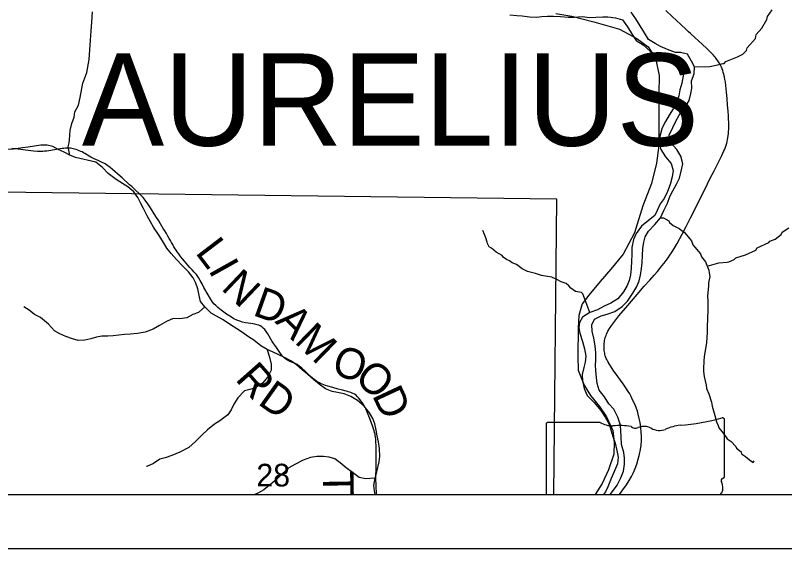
# Model space of a CAD drawing. Extents: x 0 to 34, y 0 to 22.
# Drawn here: x 6.729 to 8.15, y 14 to 14.985 of the extents above; entities that cross this region are included whole.
import ezdxf

# ---------------------------------------------------------------- set-up
doc = ezdxf.new("R2010")
doc.units = 0
for name, color, linetype in [('GM_X_Corporation_Text', 7, 'Continuous'), ('GM_X_Major_River', 7, 'Continuous'), ('GM_X_Minor_River', 7, 'Continuous'), ('GM_X_Rail_Line', 7, 'Continuous'), ('GM_X_Section_Text', 7, 'Continuous'), ('GM_X_State_Location', 7, 'Continuous'), ('GM_X_State_Route', 7, 'Continuous'), ('GM_X_State_Shield', 7, 'Continuous'), ('GM_X_Township_Road', 7, 'Continuous'), ('GM_X_Township_Road_Text', 7, 'Continuous'), ('GM_X_Township_Text', 7, 'Continuous'), ('SH_Cut_Line', 7, 'Continuous'), ('SH_Data', 7, 'Continuous')]:
    doc.layers.add(name, color=color, linetype=linetype)

msp = doc.modelspace()

# ---------------------------------------------------------------- linework, layer by layer
at = {"layer": 'GM_X_Corporation_Text'}
msp.add_line((7.8091, 14.2331), (7.7125, 14.2331), dxfattribs=at)
for points in [[(7.7093, 14.2297), (7.7093, 14.1), (8.0309, 14.1)], [(8.0389, 14.1334), (8.0389, 14.1334), (8.0389, 14.1334), (8.0389, 14.2383)]]:
    msp.add_lwpolyline(points, dxfattribs=at)
for centre, major_axis, start_param, end_param in [((7.9215, 14.506), (0.3495, 0), 4.814394, 5.042369), ((8.0353, 14.2385), (0.00367, 0), 6.197627, 7.989034), ((7.7131, 14.2301), (0.00382, 0), 1.727492, 3.291633), ((7.8321, 14.2564), (0.037, 0), 4.042888, 4.731792), ((7.8444, 14.1208), (0.133, 0), 1.404758, 1.657859), ((7.8745, 14.2311), (0.0107, 0), 3.836095, 5.185415), ((7.8902, 14.208), (0.0222, 0), 0.950623, 2.079405), ((7.9661, 14.172), (0.0703, 0), 1.699012, 2.107814), ((7.9189, 14.2397), (0.0267, 0), 4.08156, 5.145723), ((8.0381, 14.1257), (0.00568, 0), 1.883978, 3.671073), ((8.035, 14.133), (0.00393, 0), 5.05454, 6.418171), ((8.0019, 14.1125), (0.0341, 0), 5.934695, 6.695948), ((8.0521, 14.0896), (0.0248, 0), 2.387724, 2.589166)]:
    msp.add_ellipse(centre, major_axis=major_axis, ratio=0.8, start_param=start_param, end_param=end_param, dxfattribs=at)
at = {"layer": 'GM_X_Major_River'}
for points in [[(7.6424, 14.9858), (7.6553, 14.9844), (7.6648, 14.9838), (7.6784, 14.9825), (7.6917, 14.9819), (7.7015, 14.9828), (7.7118, 14.9837), (7.7232, 14.9835), (7.7357, 14.9829), (7.7501, 14.9819), (7.7615, 14.9817), (7.7766, 14.9827)], [(7.7766, 14.9827), (7.7895, 14.9813), (7.8013, 14.9815), (7.8138, 14.9824), (7.8236, 14.9825), (7.8377, 14.9801), (7.8506, 14.9765), (7.8599, 14.9637), (7.8684, 14.9494), (7.8754, 14.9385), (7.8888, 14.9307), (7.9015, 14.9191), (7.9114, 14.9117), (7.924, 14.9065), (7.9339, 14.9033), (7.9465, 14.8993), (7.956, 14.8967), (7.9633, 14.8847), (7.9627, 14.8733), (7.9603, 14.86), (7.9566, 14.8474), (7.9545, 14.8364), (7.9505, 14.8246), (7.9442, 14.812), (7.9368, 14.8009), (7.9298, 14.789), (7.9235, 14.7772), (7.9195, 14.762), (7.9182, 14.7498), (7.9214, 14.737), (7.9299, 14.7238), (7.9403, 14.7114), (7.9443, 14.6982), (7.9425, 14.6864), (7.9382, 14.6727), (7.9338, 14.6598), (7.9272, 14.6464), (7.9201, 14.6368), (7.9142, 14.6246), (7.9101, 14.6151), (7.8955, 14.6035), (7.8854, 14.5958), (7.8757, 14.582), (7.8709, 14.5709), (7.8677, 14.5561), (7.8679, 14.5436), (7.8673, 14.5303), (7.8663, 14.5189), (7.865, 14.5056), (7.8625, 14.4954), (7.8588, 14.4858), (7.8525, 14.474), (7.8421, 14.4613), (7.8289, 14.4532), (7.8165, 14.4477), (7.8041, 14.4411), (7.7901, 14.4363), (7.7766, 14.4278), (7.7707, 14.4179), (7.77, 14.408), (7.7717, 14.3978), (7.7764, 14.3823), (7.7804, 14.3687), (7.7829, 14.3555), (7.7815, 14.3441), (7.779, 14.3346), (7.7761, 14.3216), (7.7767, 14.3091), (7.7799, 14.2955), (7.7854, 14.2831), (7.7981, 14.2696), (7.8104, 14.255), (7.8185, 14.2426), (7.8259, 14.2301), (7.8287, 14.2192), (7.8323, 14.2071), (7.837, 14.1946), (7.8398, 14.181), (7.8427, 14.1689), (7.8409, 14.1564), (7.8354, 14.1438), (7.8292, 14.1297), (7.8233, 14.1144), (7.8189, 14.1049), (7.8154, 14.1)], [(7.8279, 14.1), (7.834, 14.1077), (7.8407, 14.1173), (7.8474, 14.1307), (7.8521, 14.1429), (7.8542, 14.1558), (7.8544, 14.1668), (7.8532, 14.1774), (7.8488, 14.1925), (7.8478, 14.2069), (7.8473, 14.2168), (7.8468, 14.2278), (7.8417, 14.2425), (7.8346, 14.2576), (7.8254, 14.2673), (7.8173, 14.2801), (7.8076, 14.2928), (7.8037, 14.3049), (7.8024, 14.3163), (7.8011, 14.3292), (7.8005, 14.3386), (7.8012, 14.3481), (7.801, 14.3618), (7.7997, 14.3747), (7.7972, 14.3887), (7.7944, 14.4019), (7.7938, 14.4136), (7.799, 14.4236), (7.8111, 14.4298), (7.822, 14.433), (7.836, 14.4377), (7.8499, 14.447), (7.8596, 14.457), (7.8693, 14.4716), (7.8767, 14.4842), (7.8811, 14.4948), (7.8836, 14.5051), (7.8857, 14.5173), (7.8867, 14.5279), (7.8876, 14.5416), (7.8882, 14.5545), (7.8896, 14.5663), (7.8925, 14.5758), (7.8984, 14.5865), (7.91, 14.5988), (7.9204, 14.6111), (7.9271, 14.6244), (7.9337, 14.6382), (7.9381, 14.6504), (7.9433, 14.661), (7.9499, 14.6733), (7.9555, 14.6843), (7.9591, 14.6969), (7.9619, 14.711), (7.9579, 14.725), (7.9509, 14.7374), (7.9394, 14.7501), (7.9369, 14.7637), (7.9432, 14.7779), (7.9483, 14.7885), (7.9554, 14.8008), (7.9654, 14.8142), (7.9736, 14.8279), (7.9768, 14.8409), (7.9786, 14.8504), (7.9777, 14.864), (7.9828, 14.877), (7.9834, 14.8899), (7.9779, 14.9001), (7.9705, 14.9132), (7.9576, 14.9165), (7.9481, 14.9163), (7.9336, 14.9218), (7.9207, 14.9277), (7.9107, 14.9329), (7.8985, 14.9403), (7.8911, 14.9524), (7.883, 14.9659), (7.8749, 14.9787), (7.8664, 14.9907)]]:
    msp.add_lwpolyline(points, dxfattribs=at)
at = {"layer": 'GM_X_Minor_River'}
for points in [[(7.9834, 14.8899), (8.0117, 14.8906), (8.0235, 14.893), (8.0356, 14.8959), (8.0382, 14.8963), (8.0412, 14.8998), (8.0631, 14.9081), (8.0725, 14.9132), (8.0796, 14.9201), (8.081, 14.9247), (8.0959, 14.942), (8.0976, 14.9497), (8.1081, 14.9616), (8.1173, 14.9773), (8.1183, 14.9827), (8.1272, 14.9953)], [(6.8294, 14.7267), (6.8261, 14.7419), (6.8283, 14.7492), (6.8289, 14.7553), (6.8298, 14.772), (6.8333, 14.785), (6.8377, 14.7972), (6.8386, 14.8067), (6.8456, 14.819), (6.8484, 14.8331), (6.8533, 14.8598), (6.8609, 14.8796), (6.8651, 14.9033), (6.8675, 14.939), (6.8687, 14.9565), (6.8699, 14.9721), (6.8711, 14.9915)], [(6.8402, 14.7225), (6.8294, 14.7267), (6.8189, 14.732), (6.8077, 14.7374), (6.798, 14.7427), (6.7878, 14.7449), (6.7757, 14.7453), (6.7642, 14.7435), (6.7524, 14.7416), (6.7417, 14.7405), (6.7302, 14.7382), (6.7207, 14.7374), (6.7097, 14.7382), (6.6988, 14.7424), (6.6887, 14.7465), (6.677, 14.7481), (6.6663, 14.7481), (6.6554, 14.7504), (6.6437, 14.7538), (6.6147, 14.7804)], [(7.3933, 14.1), (7.3921, 14.1069), (7.3913, 14.1168), (7.3933, 14.13), (7.3964, 14.1417), (7.4008, 14.1605), (7.4019, 14.1704), (7.4013, 14.1852), (7.3994, 14.1971), (7.3975, 14.2081), (7.3956, 14.2189), (7.3926, 14.2307), (7.3892, 14.2404), (7.3831, 14.2505), (7.3729, 14.263), (7.3607, 14.2737), (7.3484, 14.2809), (7.3364, 14.2859), (7.324, 14.2886), (7.3138, 14.2905), (7.3018, 14.2951), (7.2899, 14.3035), (7.2799, 14.3115), (7.2682, 14.3225), (7.2586, 14.3305), (7.2482, 14.3396), (7.2375, 14.3468), (7.2263, 14.3533), (7.2039, 14.3632), (7.1941, 14.3677), (7.1822, 14.3746), (7.1693, 14.3849), (7.1592, 14.3913), (7.1485, 14.3989), (7.1377, 14.4058), (7.1243, 14.4146), (7.1124, 14.4223), (7.1002, 14.4295), (7.0905, 14.4348), (7.0787, 14.4463), (7.0711, 14.4564), (7.0684, 14.4675), (7.0658, 14.4801), (7.0624, 14.4905), (7.0574, 14.5002), (7.0487, 14.5115), (7.0384, 14.5218), (7.0267, 14.534), (7.0164, 14.545), (7.0088, 14.5551), (7.0009, 14.5687), (6.9933, 14.5804), (6.9839, 14.594), (6.9782, 14.6037), (6.9721, 14.6149), (6.9658, 14.6281), (6.96, 14.6385), (6.9551, 14.6486), (6.9474, 14.6587), (6.9364, 14.6682), (6.9267, 14.6743), (6.9148, 14.6815), (6.9004, 14.6927), (6.8898, 14.7041), (6.8776, 14.714), (6.8402, 14.7225)], [(7.9204, 14.6111), (7.9263, 14.611), (7.9358, 14.6052), (7.937, 14.6022), (7.9443, 14.597), (7.955, 14.591), (7.965, 14.5836), (7.9778, 14.5682), (7.9802, 14.5611), (7.9946, 14.5446), (7.9962, 14.5389), (8.0036, 14.5299), (8.0099, 14.5144), (8.0104, 14.5095), (8.012, 14.5027), (8.0095, 14.4909), (8.0096, 14.4855), (8.0077, 14.4665), (8.0079, 14.457), (8.0078, 14.4403), (8.0068, 14.4099), (8.007, 14.3993), (8.0054, 14.3806), (8.0013, 14.3543), (8.001, 14.3467), (7.9998, 14.3323), (7.9999, 14.327), (8.0012, 14.3179), (8.0052, 14.3016), (8.0057, 14.2959), (8.0101, 14.2861), (8.0149, 14.2702), (8.0158, 14.2634), (8.021, 14.246), (8.0242, 14.2343), (8.0274, 14.2271), (8.0282, 14.2229), (8.034, 14.2162), (8.0422, 14.206), (8.0438, 14.203), (8.0514, 14.1978), (8.06, 14.1889), (8.0611, 14.1858), (8.0696, 14.1787), (8.0704, 14.1753), (8.0774, 14.1701), (8.0851, 14.1638), (8.0893, 14.1608), (8.092, 14.159), (8.0934, 14.162)], [(7.7901, 14.4363), (7.7772, 14.4709), (7.7745, 14.4731), (7.7638, 14.4752), (7.7592, 14.4782), (7.755, 14.4811), (7.7515, 14.4853), (7.7461, 14.4897), (7.737, 14.4926), (7.7301, 14.4963), (7.7197, 14.5011), (7.7117, 14.5025), (7.7007, 14.5046), (7.6896, 14.5082), (7.6747, 14.5118), (7.6652, 14.5166), (7.6548, 14.5248), (7.6467, 14.5281), (7.6418, 14.5314), (7.6364, 14.534), (7.6299, 14.5384), (7.6283, 14.5414), (7.6172, 14.5474), (7.6083, 14.5552), (7.6041, 14.5574), (7.6013, 14.5634), (7.6002, 14.5661), (7.5977, 14.574), (7.5954, 14.5801), (7.5926, 14.5876)], [(8.0069, 14.5218), (8.0283, 14.528), (8.0438, 14.529), (8.0468, 14.5294), (8.057, 14.5342), (8.06, 14.5372), (8.0777, 14.5428), (8.0966, 14.5515), (8.0992, 14.5553), (8.1206, 14.5652), (8.1229, 14.5679), (8.1323, 14.5718), (8.1435, 14.5803), (8.1457, 14.5846), (8.1577, 14.5927)], [(7.0787, 14.4463), (7.0673, 14.436), (7.0566, 14.4322), (7.0457, 14.4265), (7.0327, 14.4247), (7.0206, 14.4248), (7.0078, 14.4195), (6.995, 14.412), (6.9834, 14.4055), (6.9688, 14.4), (6.9543, 14.3975), (6.9417, 14.3964), (6.9306, 14.3956), (6.9199, 14.3941), (6.9096, 14.393), (6.8994, 14.3922), (6.8883, 14.3922), (6.8784, 14.3907), (6.868, 14.3876), (6.8573, 14.3849), (6.8448, 14.3846), (6.8346, 14.3873), (6.8218, 14.3915), (6.811, 14.3965), (6.8013, 14.4025), (6.7903, 14.4143), (6.7752, 14.4266), (6.764, 14.4323), (6.754, 14.4406), (6.7443, 14.4467)], [(7.1941, 14.3677), (7.1989, 14.3512), (7.2012, 14.3409), (7.2012, 14.3295), (7.1954, 14.3175), (7.1851, 14.3057), (7.1727, 14.297), (7.1619, 14.294), (7.1519, 14.2913), (7.1401, 14.2788), (7.1321, 14.2666), (7.1272, 14.2565), (7.1211, 14.2468), (7.1067, 14.2363), (7.0966, 14.2298), (7.0837, 14.2193), (7.0739, 14.2101), (7.0613, 14.198), (7.0491, 14.187), (7.0325, 14.1781), (7.0178, 14.1718), (7.0055, 14.1677), (6.9955, 14.165), (6.9839, 14.1574), (6.9719, 14.1518), (6.9711, 14.1518)], [(7.3933, 14.13), (7.3758, 14.1287), (7.3641, 14.1314), (7.3519, 14.1406), (7.34, 14.1494), (7.3289, 14.1585), (7.3189, 14.1661), (7.3088, 14.1691), (7.2982, 14.1699), (7.286, 14.1699), (7.2742, 14.1684), (7.2607, 14.1632), (7.2452, 14.1554), (7.234, 14.1493), (7.2214, 14.1384), (7.212, 14.1285), (7.201, 14.119), (7.1877, 14.1088), (7.178, 14.1031), (7.171, 14.1)]]:
    msp.add_lwpolyline(points, dxfattribs=at)
at = {"layer": 'GM_X_Rail_Line'}
for points in [[(4.5781, 14.1), (8.76, 14.1), (8.766, 14.6043), (8.767, 14.6265), (8.77, 15.1835), (8.7708, 15.6025), (8.369, 15.6108), (7.8392, 15.6096), (7.7355, 15.6105), (7.7434, 15.892), (7.7526, 15.9181), (7.756, 15.9342), (7.7538, 15.9954), (7.7446, 16.1373), (7.7377, 16.1663), (7.7376, 16.622), (7.6814, 16.6224), (7.149, 16.6283), (5.9824, 16.6436)], [(7.7272, 14.9881), (7.7567, 14.9837), (7.7973, 14.9733), (7.845, 14.9594), (7.8767, 14.9422), (7.8976, 14.9267), (7.9115, 14.9056), (7.9183, 14.8736), (7.9176, 14.8404), (7.9176, 14.7444), (7.9132, 14.7119), (7.9043, 14.6743), (7.8881, 14.6329), (7.8723, 14.583), (7.8516, 14.5439), (7.8291, 14.5163), (7.8091, 14.4934), (7.7883, 14.4683), (7.7759, 14.452), (7.77, 14.4306), (7.7685, 14.407), (7.7678, 14.3553), (7.7685, 14.3295), (7.7796, 14.3021), (7.7914, 14.2829), (7.8077, 14.2623), (7.8209, 14.2431), (7.8328, 14.218), (7.835, 14.1958), (7.8342, 14.1744), (7.8246, 14.1456), (7.8128, 14.1205), (7.8001, 14.1)]]:
    msp.add_lwpolyline(points, dxfattribs=at)
at = {"layer": 'GM_X_State_Route'}
for points in [[(7.9761, 14.9513), (7.9726, 14.9544), (7.9708, 14.9561), (7.9681, 14.9586), (7.958, 14.9678), (7.9423, 14.9827), (7.9304, 14.9937)], [(7.8447, 14.1), (7.8512, 14.1085), (7.8577, 14.1177), (7.8627, 14.1256), (7.867, 14.1332), (7.8706, 14.1405), (7.8738, 14.148), (7.8768, 14.1562), (7.8796, 14.1651), (7.8819, 14.1742), (7.8835, 14.1828), (7.8847, 14.1908), (7.8853, 14.1989), (7.8855, 14.2071), (7.8851, 14.2152), (7.8843, 14.2239), (7.8829, 14.2332), (7.8815, 14.2405), (7.8795, 14.2484), (7.8779, 14.2538), (7.8763, 14.2585), (7.8736, 14.2655), (7.8716, 14.2701), (7.8679, 14.278), (7.8659, 14.2819), (7.8638, 14.2857), (7.861, 14.2905), (7.8568, 14.2972), (7.8556, 14.2991), (7.8517, 14.3045), (7.8418, 14.318), (7.8335, 14.3295), (7.8281, 14.3377), (7.8259, 14.3412), (7.8239, 14.3445), (7.8231, 14.3461), (7.8221, 14.3477), (7.8212, 14.3493), (7.8205, 14.351), (7.8195, 14.3533), (7.8186, 14.356), (7.818, 14.3584), (7.8175, 14.361), (7.8171, 14.3633), (7.8168, 14.3659), (7.8164, 14.3704), (7.8163, 14.3731), (7.8163, 14.3757), (7.8165, 14.379), (7.8169, 14.3817), (7.8172, 14.3843), (7.8178, 14.3868), (7.8185, 14.3893), (7.8192, 14.3913), (7.8201, 14.3937), (7.8209, 14.3959), (7.8235, 14.4014), (7.8266, 14.4067), (7.8306, 14.4129), (7.8361, 14.4204), (7.8439, 14.43), (7.8601, 14.4489), (7.8774, 14.4692), (7.8907, 14.4848), (7.9008, 14.4961), (7.9091, 14.505), (7.9148, 14.5119), (7.9194, 14.5174), (7.9234, 14.5224), (7.9272, 14.5273), (7.9314, 14.5324), (7.9347, 14.537), (7.9381, 14.5421), (7.941, 14.5463), (7.946, 14.5542), (7.9512, 14.5633), (7.9606, 14.5809), (7.9681, 14.5952), (7.976, 14.6107), (8.0019, 14.6623), (8.0133, 14.6857), (8.019, 14.6967), (8.0265, 14.7111), (8.034, 14.7261), (8.0379, 14.7346), (8.0393, 14.7378), (8.0407, 14.7416), (8.0418, 14.745), (8.0429, 14.7488), (8.0437, 14.7519), (8.0445, 14.7555), (8.0451, 14.759), (8.0458, 14.7631), (8.0461, 14.7663), (8.0464, 14.7704), (8.0466, 14.7745), (8.0467, 14.7785), (8.0467, 14.7832), (8.0467, 14.7879), (8.0464, 14.7932), (8.0461, 14.7991), (8.0455, 14.8081), (8.0445, 14.8189), (8.0436, 14.8312), (8.0423, 14.843), (8.0418, 14.8492), (8.0412, 14.8553), (8.0405, 14.8616), (8.0397, 14.8664), (8.0388, 14.8713), (8.0379, 14.8755), (8.0367, 14.8797), (8.0356, 14.8833), (8.0333, 14.8892), (8.0314, 14.8932), (8.0292, 14.897), (8.0265, 14.9012), (8.0235, 14.9052), (8.0215, 14.9077), (8.0199, 14.9096), (8.0183, 14.9114), (8.0136, 14.9164), (8.011, 14.9191), (8.006, 14.9237), (7.9982, 14.9309), (7.9768, 14.9506), (7.9761, 14.9513)]]:
    msp.add_lwpolyline(points, dxfattribs=at)
at = {"layer": 'GM_X_State_Shield'}
msp.add_lwpolyline([(6.6856, 14.1), (7.7238, 14.1), (7.7293, 14.6454), (6.698, 14.6582)], close=True, dxfattribs=at)
at = {"layer": 'GM_X_Township_Road'}
msp.add_lwpolyline([(7.3965, 14.1), (7.3961, 14.1026), (7.3957, 14.1066), (7.3954, 14.1107), (7.3952, 14.1146), (7.3951, 14.1203), (7.3949, 14.1264), (7.3954, 14.155), (7.3955, 14.173), (7.3953, 14.1885), (7.3948, 14.1985), (7.3946, 14.2019), (7.3942, 14.2058), (7.3936, 14.2087), (7.3932, 14.2114), (7.3925, 14.2142), (7.3916, 14.2174), (7.3885, 14.2268), (7.3842, 14.2385), (7.3794, 14.2506), (7.3761, 14.258), (7.3735, 14.2629), (7.3693, 14.2698), (7.3654, 14.2754), (7.3627, 14.2787), (7.3604, 14.2812), (7.3582, 14.2832), (7.3554, 14.2851), (7.3521, 14.2867), (7.3484, 14.2883), (7.3439, 14.2898), (7.3406, 14.2908), (7.3374, 14.2916), (7.3339, 14.2926), (7.3304, 14.2935), (7.3253, 14.2948), (7.3151, 14.2975), (7.3061, 14.3001), (7.302, 14.3014), (7.2985, 14.3027), (7.2954, 14.3038), (7.2927, 14.3051), (7.2905, 14.3061), (7.2878, 14.3077), (7.2854, 14.309), (7.2831, 14.3107), (7.2781, 14.3144), (7.2735, 14.3185), (7.2633, 14.3285), (7.2578, 14.3336), (7.2534, 14.3371), (7.2493, 14.3398), (7.2455, 14.3418), (7.2357, 14.3459), (7.2318, 14.3479), (7.2282, 14.3502), (7.2249, 14.353), (7.2219, 14.3562), (7.2184, 14.3606), (7.211, 14.3713), (7.2035, 14.3828), (7.1952, 14.3966), (7.1921, 14.4013), (7.1894, 14.4047), (7.1868, 14.4073), (7.1839, 14.4096), (7.1812, 14.4113), (7.1784, 14.4125), (7.1755, 14.4135), (7.1712, 14.4145), (7.1638, 14.4156), (7.154, 14.417), (7.1485, 14.4182), (7.1432, 14.4198), (7.138, 14.4219), (7.1325, 14.4247), (7.1278, 14.4275), (7.1189, 14.4333), (7.1088, 14.4406), (7.1028, 14.4453), (7.0989, 14.4489), (7.0957, 14.4523), (7.0924, 14.4564), (7.0892, 14.4612), (7.0847, 14.4687), (7.0772, 14.4826), (7.0739, 14.4888), (7.0704, 14.4952), (7.0669, 14.501), (7.0634, 14.506), (7.0594, 14.5108), (7.0556, 14.5149), (7.0514, 14.5194), (7.0477, 14.5235), (7.0445, 14.5271), (7.0411, 14.5311), (7.0378, 14.5351), (7.0345, 14.5392), (7.0328, 14.5415), (7.0307, 14.5443), (7.0277, 14.5482), (7.0256, 14.5512), (7.0229, 14.5554), (7.0218, 14.5572), (7.0195, 14.5615), (7.0173, 14.5654), (7.0154, 14.5689), (7.013, 14.573), (7.0106, 14.5772), (7.0079, 14.5819), (7.0047, 14.5872), (7.0021, 14.5915), (6.9995, 14.5957), (6.9969, 14.5999), (6.9937, 14.6052), (6.9886, 14.6136), (6.9787, 14.6295), (6.9736, 14.6371), (6.9689, 14.6434), (6.9646, 14.6485), (6.9587, 14.6547), (6.9504, 14.6626), (6.9437, 14.6687), (6.9397, 14.6722), (6.9259, 14.6846), (6.9222, 14.6879), (6.9085, 14.7005), (6.9042, 14.704), (6.8996, 14.7073), (6.8944, 14.7105), (6.8878, 14.714), (6.8806, 14.7173), (6.8759, 14.7195), (6.872, 14.7214), (6.8682, 14.7232), (6.8649, 14.7251), (6.8574, 14.7296), (6.8547, 14.7313), (6.852, 14.7327), (6.8497, 14.7338), (6.8469, 14.735), (6.844, 14.7361), (6.8411, 14.737), (6.8382, 14.7378), (6.8356, 14.7384), (6.8334, 14.739), (6.8304, 14.7394), (6.8276, 14.7395), (6.8245, 14.7395), (6.8216, 14.7395), (6.8183, 14.7392), (6.815, 14.7389), (6.8115, 14.7384), (6.7907, 14.735), (6.7867, 14.7344), (6.7827, 14.7341), (6.7794, 14.7338), (6.7759, 14.7337), (6.7696, 14.7337), (6.7622, 14.7343), (6.7474, 14.7361), (6.7295, 14.7383), (6.7221, 14.7388)], dxfattribs=at)
at = {"layer": 'SH_Cut_Line'}
msp.add_lwpolyline([(4.5781, 14.1), (8.9, 14.1), (8.9, 14.624), (8.767, 14.6265), (8.77, 15.1835), (8.7708, 15.6025), (8.369, 15.6108), (7.8392, 15.6096), (7.7355, 15.6105), (7.7434, 15.892), (7.7526, 15.9181), (7.756, 15.9342), (7.7538, 15.9954), (7.7446, 16.1373), (7.7377, 16.1663), (7.7376, 16.622), (7.6814, 16.6224), (7.149, 16.6283), (5.9824, 16.6436)], dxfattribs=at)
at = {"layer": 'SH_Data'}
for p, q in [((2.1, 14.1), (8.9, 14.1)), ((2, 14), (9, 14))]:
    msp.add_line(p, q, dxfattribs=at)

# ---------------------------------------------------------------- texts
at = {"layer": 'GM_X_Section_Text'}
msp.add_text('28', height=0.04186, rotation=0, dxfattribs=at).set_placement((7.174, 14.1148))
at = {"layer": 'GM_X_State_Location'}
for s in ['s', 'r']:
    msp.add_text(s, height=0.000189, dxfattribs=at).set_placement((7.8704, 14.1163))
msp.add_text('821', height=0.000189, rotation=0, dxfattribs=at).set_placement((7.8036, 14.1025))
at = {"layer": 'GM_X_Township_Road_Text'}
for s, rotation, p in [('L', 307.3593, (7.0599, 14.5466)), ('I', 299.3169, (7.0845, 14.5146)), ('N', 316.4091, (7.1073, 14.4797)), ('D', 340.4044, (7.1655, 14.4317)), ('A', 314.1474, (7.2068, 14.4186)), ('M', 315.7458, (7.2429, 14.3815)), ('O', 341.4323, (7.3106, 14.3241)), ('R', 311.4485, (7.1335, 14.3123)), ('O', 319.4864, (7.353, 14.311)), ('D', 324.5887, (7.1748, 14.268)), ('D', 295.0563, (7.3872, 14.2836)), ('T', 270.9901, (7.2966, 14.1428))]:
    msp.add_text(s, height=0.0568, rotation=rotation, dxfattribs=at).set_placement(p)
at = {"layer": 'GM_X_Township_Text'}
msp.add_text('AURELIUS', height=0.17045, rotation=0, dxfattribs=at).set_placement((6.8517, 14.7441))

doc.saveas('drawing.dxf')
